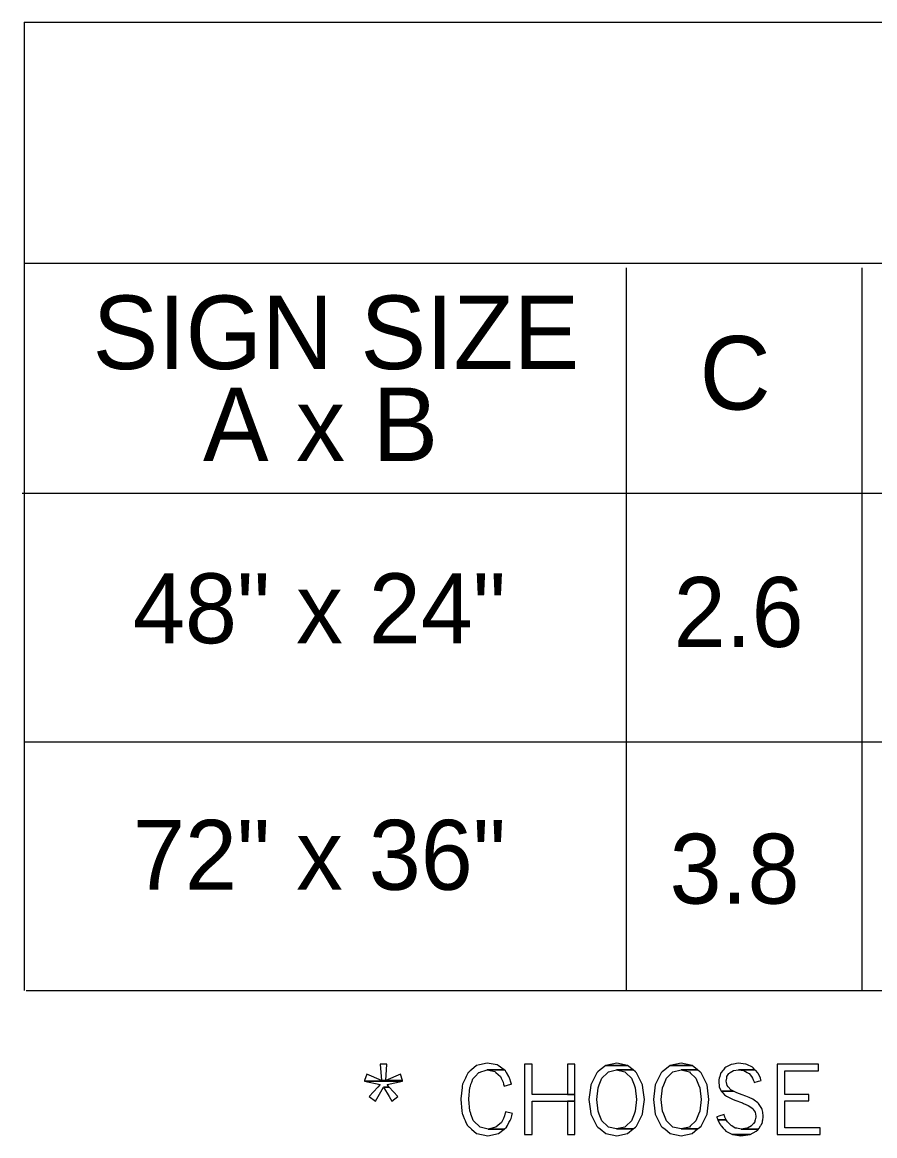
# Model space of a CAD drawing. Extents: x 0.013 to 0.187, y -0.092 to 0.261.
# Drawn here: x 0.03238 to 0.06135, y 0.0569 to 0.09473 of the extents above; entities that cross this region are included whole.
import ezdxf

# ---------------------------------------------------------------- set-up
doc = ezdxf.new("R2010")
doc.units = 0
doc.layers.add('3', color=7, linetype='Continuous')

msp = doc.modelspace()

# ---------------------------------------------------------------- linework, layer by layer
at = {"layer": '3'}
for p, q in [((0.032451, 0.094728), (0.032451, 0.061842)), ((0.032451, 0.094728), (0.186512, 0.094728)), ((0.186512, 0.086538), (0.032451, 0.086538)), ((0.052908, 0.086386), (0.052908, 0.061842)), ((0.060908, 0.086386), (0.060908, 0.061842)), ((0.032384, 0.078726), (0.186512, 0.078726)), ((0.032451, 0.070284), (0.186512, 0.070284)), ((0.032519, 0.061842), (0.186512, 0.061842))]:
    msp.add_line(p, q, dxfattribs=at)
for points in [[(0.044549, 0.059329), (0.044588, 0.058777), (0.044733, 0.058777), (0.044771, 0.059329)], [(0.047835, 0.056975), (0.048203, 0.056904), (0.048567, 0.056975), (0.048571, 0.056978), (0.048762, 0.057131), (0.048214, 0.057131), (0.047947, 0.05719), (0.047943, 0.057191), (0.047942, 0.057192), (0.047942, 0.057192), (0.047884, 0.057249), (0.047883, 0.057249), (0.047777, 0.057355), (0.047707, 0.057423), (0.047682, 0.057494), (0.047651, 0.057576), (0.04763, 0.057633), (0.047621, 0.057658), (0.047587, 0.057751), (0.047556, 0.058135), (0.047554, 0.058158), (0.047591, 0.058539), (0.04761, 0.058592), (0.04763, 0.058651), (0.047632, 0.058656), (0.047656, 0.058722), (0.047699, 0.058841), (0.047721, 0.058864), (0.04777, 0.058915), (0.0479, 0.059051), (0.047906, 0.059057), (0.048004, 0.059087), (0.048074, 0.059108), (0.048074, 0.059108), (0.048182, 0.059141), (0.048755, 0.059141), (0.048555, 0.059287), (0.048555, 0.059287), (0.048526, 0.059308), (0.048184, 0.059367), (0.048184, 0.059367), (0.047917, 0.059308), (0.04782, 0.059287), (0.047645, 0.059141), (0.047606, 0.059108), (0.047581, 0.059087), (0.047545, 0.059057), (0.047538, 0.059051), (0.047472, 0.058915), (0.047448, 0.058864), (0.047436, 0.058841), (0.047378, 0.058722), (0.047346, 0.058656), (0.047344, 0.058651), (0.047337, 0.058592), (0.047331, 0.058539), (0.047288, 0.058158), (0.047285, 0.058135), (0.047325, 0.057751), (0.047335, 0.057658), (0.047338, 0.057633), (0.047364, 0.057576), (0.0474, 0.057494), (0.047432, 0.057423), (0.047462, 0.057355), (0.04751, 0.057249), (0.047575, 0.057192), (0.047577, 0.057191), (0.047578, 0.05719), (0.047645, 0.057131), (0.04782, 0.056978)], [(0.048742, 0.058651), (0.048757, 0.058592), (0.048985, 0.058651), (0.049006, 0.058656), (0.048986, 0.058722), (0.048986, 0.058722), (0.04895, 0.058841), (0.048944, 0.058864), (0.048914, 0.058915), (0.048835, 0.059051), (0.048834, 0.059051), (0.048831, 0.059057), (0.048813, 0.059087), (0.048801, 0.059108), (0.048755, 0.059141), (0.048182, 0.059141), (0.048339, 0.059108), (0.048442, 0.059087), (0.048474, 0.059057), (0.048481, 0.059051), (0.04863, 0.058915), (0.048654, 0.058864), (0.048665, 0.058841), (0.048724, 0.058722), (0.048741, 0.058656)], [(0.049448, 0.058076), (0.049448, 0.056942), (0.049707, 0.056942), (0.049707, 0.058076), (0.051166, 0.058076), (0.051166, 0.058308), (0.049707, 0.058308), (0.049707, 0.059329), (0.049448, 0.059329), (0.049448, 0.058308)], [(0.050906, 0.059329), (0.050906, 0.058308), (0.051166, 0.058308), (0.051166, 0.059329)], [(0.052211, 0.05698), (0.052582, 0.056903), (0.052953, 0.05698), (0.053142, 0.057133), (0.052581, 0.057133), (0.0523, 0.057197), (0.052271, 0.057225), (0.052078, 0.057409), (0.051988, 0.057637), (0.051948, 0.057738), (0.051906, 0.058135), (0.051948, 0.058532), (0.051988, 0.058633), (0.052078, 0.058861), (0.052271, 0.059045), (0.0523, 0.059073), (0.052581, 0.059138), (0.053142, 0.059138), (0.052953, 0.05929), (0.052211, 0.05929), (0.052022, 0.059138), (0.051942, 0.059073), (0.051908, 0.059045), (0.051817, 0.058861), (0.051704, 0.058633), (0.051691, 0.058532), (0.051639, 0.058135), (0.051691, 0.057738), (0.051704, 0.057637), (0.051817, 0.057409), (0.051908, 0.057225), (0.051942, 0.057197), (0.052022, 0.057133)], [(0.052582, 0.059367), (0.052211, 0.05929), (0.052953, 0.05929)], [(0.052863, 0.057197), (0.052581, 0.057133), (0.053142, 0.057133), (0.053222, 0.057197), (0.053222, 0.057197), (0.053256, 0.057225), (0.053347, 0.057409), (0.05346, 0.057637), (0.053473, 0.057738), (0.053525, 0.058135), (0.053473, 0.058532), (0.05346, 0.058633), (0.053347, 0.058861), (0.053256, 0.059045), (0.053222, 0.059073), (0.053222, 0.059073), (0.053142, 0.059138), (0.052581, 0.059138), (0.052863, 0.059073), (0.052892, 0.059045), (0.053084, 0.058861), (0.053174, 0.058633), (0.053214, 0.058532), (0.053256, 0.058135), (0.053214, 0.057738), (0.053174, 0.057637), (0.053084, 0.057409), (0.052892, 0.057225)], [(0.054402, 0.05698), (0.054773, 0.056903), (0.055145, 0.05698), (0.055333, 0.057133), (0.054773, 0.057133), (0.054491, 0.057197), (0.054462, 0.057225), (0.05427, 0.057409), (0.054179, 0.057637), (0.05414, 0.057738), (0.054098, 0.058135), (0.05414, 0.058532), (0.054179, 0.058633), (0.05427, 0.058861), (0.054462, 0.059045), (0.054491, 0.059073), (0.054773, 0.059138), (0.055333, 0.059138), (0.055145, 0.05929), (0.054402, 0.05929), (0.054213, 0.059138), (0.054133, 0.059073), (0.054099, 0.059045), (0.054008, 0.058861), (0.053895, 0.058633), (0.053882, 0.058532), (0.05383, 0.058135), (0.053882, 0.057738), (0.053895, 0.057637), (0.054008, 0.057409), (0.054099, 0.057225), (0.054133, 0.057197), (0.054213, 0.057133)], [(0.054773, 0.059367), (0.054402, 0.05929), (0.055145, 0.05929)], [(0.055054, 0.057197), (0.054773, 0.057133), (0.055333, 0.057133), (0.055414, 0.057197), (0.055413, 0.057197), (0.055448, 0.057225), (0.055539, 0.057409), (0.055652, 0.057637), (0.055665, 0.057738), (0.055716, 0.058135), (0.055665, 0.058532), (0.055652, 0.058633), (0.055539, 0.058861), (0.055448, 0.059045), (0.055414, 0.059073), (0.055413, 0.059073), (0.055333, 0.059138), (0.054772, 0.059138), (0.055054, 0.059073), (0.055083, 0.059045), (0.055276, 0.058861), (0.055366, 0.058633), (0.055406, 0.058532), (0.055448, 0.058135), (0.055406, 0.057738), (0.055366, 0.057637), (0.055276, 0.057409), (0.055083, 0.057225)], [(0.056115, 0.058465), (0.056138, 0.058415), (0.056553, 0.058415), (0.056456, 0.058465), (0.056367, 0.05857), (0.056335, 0.058609), (0.056312, 0.058715), (0.056303, 0.058756), (0.056307, 0.058784), (0.056311, 0.058806), (0.05632, 0.058856), (0.05632, 0.058862), (0.056329, 0.05891), (0.056398, 0.059016), (0.056411, 0.059034), (0.056422, 0.059041), (0.056438, 0.059051), (0.056548, 0.059118), (0.05655, 0.059119), (0.056721, 0.059146), (0.057279, 0.059146), (0.057221, 0.059208), (0.057201, 0.059229), (0.057, 0.059325), (0.056969, 0.05934), (0.056714, 0.059367), (0.056714, 0.059367), (0.056557, 0.05934), (0.056468, 0.059325), (0.056296, 0.059229), (0.056258, 0.059208), (0.056207, 0.059146), (0.056185, 0.059119), (0.056184, 0.059118), (0.056129, 0.059051), (0.056121, 0.059041), (0.056119, 0.059034), (0.056114, 0.059016), (0.056082, 0.05891), (0.056068, 0.058862), (0.056067, 0.058856), (0.056052, 0.058806), (0.056053, 0.058784), (0.056055, 0.058756), (0.056058, 0.058715), (0.056065, 0.058609), (0.056068, 0.05857)], [(0.05724, 0.058756), (0.057256, 0.058715), (0.057397, 0.058756), (0.057493, 0.058784), (0.057486, 0.058806), (0.057471, 0.058856), (0.057469, 0.058862), (0.057443, 0.05891), (0.057388, 0.059016), (0.057378, 0.059034), (0.057375, 0.059041), (0.05737, 0.059051), (0.057306, 0.059118), (0.057305, 0.059119), (0.057279, 0.059146), (0.05672, 0.059146), (0.056892, 0.059119), (0.056902, 0.059118), (0.057021, 0.059051), (0.057039, 0.059041), (0.057051, 0.059034), (0.057083, 0.059016), (0.057161, 0.05891), (0.057197, 0.058862), (0.057202, 0.058856), (0.057221, 0.058806), (0.057229, 0.058784)], [(0.058038, 0.057172), (0.058038, 0.056942), (0.059501, 0.056942), (0.059501, 0.057172), (0.0583, 0.057172), (0.0583, 0.058085), (0.059111, 0.058085), (0.059111, 0.058306), (0.0583, 0.058306), (0.0583, 0.059103), (0.059445, 0.059103), (0.059445, 0.059329), (0.058038, 0.059329), (0.058038, 0.059103), (0.058038, 0.058306), (0.058038, 0.058085)], [(0.044016, 0.058777), (0.04401, 0.058759), (0.04531, 0.058759), (0.045304, 0.058777), (0.044588, 0.058777), (0.044087, 0.059)], [(0.044175, 0.058232), (0.044384, 0.058078), (0.044474, 0.058232), (0.044662, 0.058553), (0.044855, 0.058553), (0.044778, 0.058639), (0.04531, 0.058759), (0.04401, 0.058759), (0.044543, 0.058639), (0.044465, 0.058553)], [(0.045234, 0.059), (0.044733, 0.058777), (0.045304, 0.058777)], [(0.044847, 0.058232), (0.044937, 0.058078), (0.045145, 0.058232), (0.044856, 0.058553), (0.044662, 0.058553)], [(0.057003, 0.057156), (0.056811, 0.057131), (0.057399, 0.057131), (0.057415, 0.057156), (0.057422, 0.057166), (0.057468, 0.057236), (0.057478, 0.057251), (0.057478, 0.057251), (0.05749, 0.057269), (0.057522, 0.057318), (0.057532, 0.057373), (0.057538, 0.057406), (0.057544, 0.057446), (0.057559, 0.057531), (0.057561, 0.057541), (0.057562, 0.057546), (0.057565, 0.057563), (0.057544, 0.057702), (0.05753, 0.057798), (0.05751, 0.05783), (0.057448, 0.057933), (0.057406, 0.058001), (0.057383, 0.058018), (0.057253, 0.058113), (0.057209, 0.058145), (0.057085, 0.058198), (0.056966, 0.05825), (0.056845, 0.058293), (0.056663, 0.058359), (0.056553, 0.058415), (0.056138, 0.058415), (0.05619, 0.058359), (0.056251, 0.058293), (0.056319, 0.05825), (0.0564, 0.058198), (0.056522, 0.058145), (0.056595, 0.058113), (0.056853, 0.058018), (0.056892, 0.058001), (0.05705, 0.057933), (0.057204, 0.05783), (0.057224, 0.057798), (0.057286, 0.057702), (0.057307, 0.057563), (0.057309, 0.057546), (0.057308, 0.057541), (0.057306, 0.057531), (0.057288, 0.057446), (0.05728, 0.057406), (0.057273, 0.057373), (0.057228, 0.057318), (0.057189, 0.057269), (0.057173, 0.057251), (0.057162, 0.057236), (0.057023, 0.057166)], [(0.050906, 0.058076), (0.050906, 0.056942), (0.051166, 0.056942), (0.051166, 0.058076)], [(0.048472, 0.05719), (0.048214, 0.057131), (0.048762, 0.057131), (0.048836, 0.05719), (0.048837, 0.057191), (0.048837, 0.057191), (0.048839, 0.057192), (0.048868, 0.057249), (0.048923, 0.057355), (0.048959, 0.057423), (0.048996, 0.057494), (0.049019, 0.057576), (0.049036, 0.057633), (0.049043, 0.057658), (0.048804, 0.057711), (0.048791, 0.057658), (0.048785, 0.057633), (0.048772, 0.057576), (0.048731, 0.057494), (0.048697, 0.057423), (0.048664, 0.057355), (0.048541, 0.057249), (0.048474, 0.057192), (0.048473, 0.057191)], [(0.055985, 0.057531), (0.056016, 0.057446), (0.056304, 0.057446), (0.05626, 0.057531), (0.056257, 0.057541), (0.056255, 0.057546), (0.05625, 0.057563), (0.056249, 0.057563), (0.056231, 0.057621), (0.056231, 0.057621), (0.05605, 0.057563), (0.055998, 0.057546), (0.055981, 0.057541)], [(0.056293, 0.057064), (0.056523, 0.056947), (0.057119, 0.056947), (0.057317, 0.057064), (0.057379, 0.0571), (0.057399, 0.057131), (0.056811, 0.057131), (0.056669, 0.057156), (0.056669, 0.057156), (0.056613, 0.057166), (0.056498, 0.057236), (0.056475, 0.057251), (0.056445, 0.057269), (0.056402, 0.057318), (0.056353, 0.057373), (0.056353, 0.057373), (0.056324, 0.057406), (0.056304, 0.057446), (0.056015, 0.057446), (0.056036, 0.057406), (0.056053, 0.057373), (0.056081, 0.057318), (0.056107, 0.057269), (0.056117, 0.057251), (0.05613, 0.057236), (0.056196, 0.057166), (0.056206, 0.057156), (0.05623, 0.057131), (0.056258, 0.0571)], [(0.056527, 0.056946), (0.056805, 0.056903), (0.057118, 0.056946), (0.057119, 0.056947), (0.056522, 0.056947)]]:
    msp.add_lwpolyline(points, close=True, dxfattribs=at)

# ---------------------------------------------------------------- texts
for s, height, p in [('SIGN SIZE', 0.0024998, (0.034775, 0.082946)), ('C', 0.0025, (0.0554, 0.081571)), ('A x B', 0.0024998, (0.038525, 0.079821)), ('48" x 24"', 0.0023752, (0.036146, 0.073633)), ('2.6', 0.0023752, (0.054519, 0.073508)), ('72" x 36"', 0.0023752, (0.036146, 0.065258)), ('3.8', 0.0023752, (0.054381, 0.064787))]:
    msp.add_text(s, height=height, dxfattribs=at).set_placement(p)

doc.saveas('drawing.dxf')
